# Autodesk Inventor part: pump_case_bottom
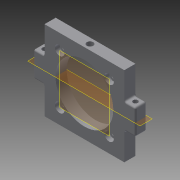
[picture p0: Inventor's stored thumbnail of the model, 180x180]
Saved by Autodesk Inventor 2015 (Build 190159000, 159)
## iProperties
Created: 2017-07
Part Number: pump_case_bottom
Material: Generic
Document SubType Name: Modeling
Designer: jonas
Density: 1 g/cm^3
Appearance: Default
Author: jonas
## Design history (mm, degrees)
workplane "Work Plane3"
workplane "Work Plane4"
workplane "Work Plane6"
sketch "Sketch1"
  geometry: L1 (-25, -25)-(25, -25); L2 (25, -25)-(25, 25); L3 (25, 25)-(-25, 25); L4 (-25, 25)-(-25, -25); L5 (-25, -25)-(25, 25); L6 (25, -25)-(-25, 25); L7 (-15.5, 15.5)-(-15.5, 25); L8 (15.5, 15.5)-(15.5, 25); L9 (-15.5, 25)-(-25, 25); L10 (-25, 25)-(-25, 0); L11 (15.5, 25)-(25, 25); L12 (25, 25)-(25, 0); L13 (-15.5, 25)-(15.5, 25); L14 (-25, 0)-(-25, -25); L15 (-25, -25)-(25, -25); L16 (25, -25)-(25, 0); C1 r 1.5 at (-15.5, 15.5) reference; C2 r 1.5 at (-15.5, -15.5) reference; C3 r 1.5 at (15.5, -15.5) reference; C4 r 1.5 at (15.5, 15.5) reference; C5 r 14.1 at (0, 0) reference; C6 r 18.1 at (0, 0); C7 r 17.1 at (0, 0) reference; 1 further point
  constraints: 32 end point, 4 collinear, 4 midpoint, 3 perpendicular, 2 centre point, 2 equal length, 2 parallel, 2 point on line, 1 coincident, 1 horizontal, 1 vertical, 2 other
  dimensions: "d74" = 50 distance of L2.end L3.end; "d126" = 50 distance of L1.end L2.end (derived); "d134" = 1 radial gap between concentric circles of C6 C7
extrude "Extrusion4" new body sketch "Sketch1" stored distance "d44" = 10; taper "d45" = 0 deg
sketch "Sketch10"
  geometry: L1 (50, 0)-(0, 0) reference; L2 (0, -7)-(50, -7) reference; L3 (25, 1.4)-(25, -8.4) reference; L4 (25, -7)-(25, 0); 1 further point
  constraints: 2 end point, 2 midpoint, 1 collinear, 1 point on line
hole "Hole7" sketch "Sketch10" at (25, -3.5) diameter "d100" = 4; stored, may be unused: countersink angle "d104" = 90 deg, drill point angle "d106" = 118 deg; dims "d101" = 6, "d102" = 5.5, "d103" = 4, "d105" = 16
sketch "Sketch12"
  geometry: L1 (25, 0)-(25, 7) reference; L2 (25, 0)-(32, 0); L3 (32, 0)-(32, 7); L4 (32, 7)-(25, 7); L5 (25, 7)-(25, 0); L6 (-25, 0)-(-25, 7) reference; L7 (0, -1.4)-(0, 8.4) reference; L8 (-25, 0)-(-25, 7); L9 (-25, 0)-(-32, 0); L10 (-32, 0)-(-32, 7); L11 (-32, 7)-(-25, 7); L12 (-25, 7)-(-25, 0); 1 further point
  constraints: 18 end point, 4 perpendicular, 2 symmetric about line, 1 vertical
extrude "Extrusion8" join sketch "Sketch12" stored distance "d116" = 16; taper "d117" = 0 deg
fillet "Fillet1" dims "d118" = 1
sketch "Sketch13"
  geometry: L1 (-32, -6)-(-32, -1) reference; L2 (-32, -1)-(-32, -6) reference; L3 (-25, 0)-(-25, -7) reference; L4 (-32, -3.5)-(-25, -3.5); L5 (0, 1.4)-(0, -8.4) reference; L6 (32, -6)-(32, -1); L7 (32, -1)-(32, -6); L8 (25, 0)-(25, -7); L9 (32, -3.5)-(25, -3.5); 3 further points
  constraints: 10 end point, 9 symmetric about line, 3 midpoint
hole "Hole9" sketch "Sketch13" at (-28.5, -3.5), (28.5, -3.5) diameter "d119" = 3; stored, may be unused: countersink angle "d123" = 90 deg, drill point angle "d125" = 118 deg; dims "d120" = 6, "d121" = 5, "d122" = 2, "d124" = 8
sketch "Sketch14"
  geometry: C1 r 1.23 at (9.5, -9.5) reference; C2 r 1.23 at (40.5, -9.5) reference; C3 r 1.23 at (40.5, -40.5) reference; C4 r 1.23 at (9.5, -40.5) reference
  constraints: 4 centre point, 8 other
hole "Hole10" sketch "Sketch14" at (40.5, -40.5), (9.5, -40.5), (40.5, -9.5), (9.5, -9.5) diameter "d127" = 3.5; stored, may be unused: countersink angle "d131" = 90 deg, drill point angle "d133" = 118 deg; dims "d128" = 6, "d129" = 6, "d130" = 3, "d132" = 8
body "Solid4"
node "Reference1"
node "Reference2"
node "Reference3"
node "Reference4"
node "Reference5"
node "Projected Loop6"
